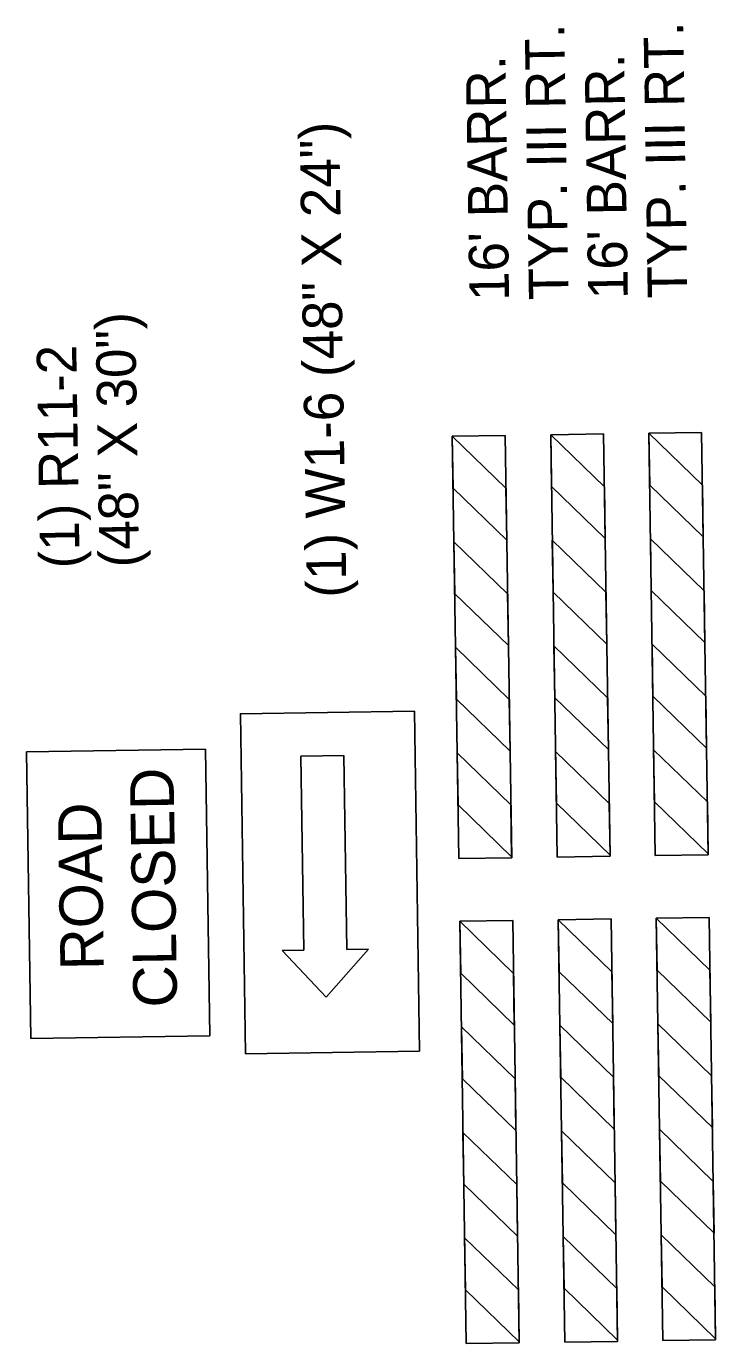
# Model space of a CAD drawing. Extents: x 1770018 to 1773492, y 718230 to 729141.
# Drawn here: x 1772247.2 to 1772351.6, y 718230.4 to 718430.1 of the extents above; entities that cross this region are included whole.
import ezdxf

# ---------------------------------------------------------------- set-up
doc = ezdxf.new("R2010")
doc.units = 0
doc.layers.add('R_MOT', color=7, linetype='Continuous')

msp = doc.modelspace()

# ---------------------------------------------------------------- linework, layer by layer
at = {"layer": 'R_MOT'}
for p, q in [((1772319.7, 718368.11), (1772311.67, 718367.99)), ((1772319.68, 718368.06), (1772319.63, 718368.11)), ((1772320.69, 718304.09), (1772319.7, 718368.11)), ((1772334.58, 718368.34), (1772326.57, 718368.22)), ((1772334.58, 718368.34), (1772326.57, 718368.22)), ((1772327.55, 718304.19), (1772326.57, 718368.22)), ((1772335.57, 718304.32), (1772334.58, 718368.34)), ((1772349.44, 718368.57), (1772341.42, 718368.45)), ((1772342.41, 718304.42), (1772341.42, 718368.45)), ((1772350.42, 718304.54), (1772349.44, 718368.57)), ((1772312.65, 718303.96), (1772311.67, 718367.99)), ((1772274.29, 718320.57), (1772247.15, 718320.15)), ((1772247.82, 718276.7), (1772247.15, 718320.15)), ((1772274.96, 718277.12), (1772274.29, 718320.57)), ((1772295.25, 718319.58), (1772288.71, 718319.48)), ((1772288.71, 718319.48), (1772289.16, 718290.1)), ((1772295.25, 718319.58), (1772295.71, 718290.2)), ((1772335.57, 718304.32), (1772327.55, 718304.19)), ((1772350.42, 718304.54), (1772342.41, 718304.42)), ((1772320.69, 718304.09), (1772312.65, 718303.96)), ((1772320.84, 718294.59), (1772312.8, 718294.47)), ((1772313.78, 718230.44), (1772312.8, 718294.47)), ((1772320.81, 718294.54), (1772320.77, 718294.59)), ((1772321.82, 718230.57), (1772320.84, 718294.59)), ((1772335.72, 718294.82), (1772327.7, 718294.7)), ((1772335.72, 718294.82), (1772327.7, 718294.7)), ((1772328.69, 718230.67), (1772327.7, 718294.7)), ((1772336.7, 718230.79), (1772335.72, 718294.82)), ((1772350.57, 718295.05), (1772342.55, 718294.92)), ((1772343.54, 718230.9), (1772342.55, 718294.92)), ((1772351.56, 718231.02), (1772350.57, 718295.05)), ((1772298.98, 718290.25), (1772292.55, 718282.97)), ((1772295.71, 718290.2), (1772298.98, 718290.25)), ((1772289.16, 718290.1), (1772285.89, 718290.05)), ((1772292.55, 718282.97), (1772285.89, 718290.05)), ((1772274.96, 718277.12), (1772247.82, 718276.7)), ((1772321.82, 718230.57), (1772313.78, 718230.44)), ((1772336.7, 718230.79), (1772328.69, 718230.67)), ((1772351.56, 718231.02), (1772343.54, 718230.9))]:
    msp.add_line(p, q, dxfattribs=at)
for points in [[(1772326.57, 718368.22), (1772326.71, 718360.35), (1772334.83, 718352.48), (1772334.71, 718360.33)], [(1772341.42, 718368.45), (1772341.57, 718360.58), (1772349.68, 718352.71), (1772349.56, 718360.55)], [(1772311.67, 718367.99), (1772311.81, 718360.12), (1772319.92, 718352.25), (1772319.8, 718360.1)], [(1772326.81, 718352.22), (1772326.96, 718344.35), (1772335.07, 718336.48), (1772334.95, 718344.33)], [(1772341.67, 718352.45), (1772341.81, 718344.58), (1772349.93, 718336.71), (1772349.81, 718344.56)], [(1772311.91, 718351.99), (1772312.06, 718344.12), (1772320.17, 718336.25), (1772320.05, 718344.1)], [(1772327.06, 718336.22), (1772327.21, 718328.35), (1772335.32, 718320.48), (1772335.2, 718328.33)], [(1772341.92, 718336.45), (1772342.06, 718328.58), (1772350.17, 718320.71), (1772350.05, 718328.56)], [(1772312.16, 718335.99), (1772312.3, 718328.12), (1772320.42, 718320.25), (1772320.3, 718328.1)], [(1772306.71, 718274.79), (1772305.92, 718326.32), (1772279.57, 718325.91), (1772280.36, 718274.39)], [(1772327.31, 718320.22), (1772327.45, 718312.35), (1772335.57, 718304.48), (1772335.45, 718312.33)], [(1772342.16, 718320.45), (1772342.31, 718312.58), (1772350.42, 718304.71), (1772350.3, 718312.56)], [(1772312.4, 718319.99), (1772312.55, 718312.12), (1772320.66, 718304.25), (1772320.54, 718312.1)], [(1772312.8, 718294.47), (1772312.94, 718286.6), (1772321.06, 718278.73), (1772320.94, 718286.57)], [(1772327.7, 718294.7), (1772327.85, 718286.82), (1772335.96, 718278.96), (1772335.84, 718286.8)], [(1772342.55, 718294.92), (1772342.7, 718287.05), (1772350.81, 718279.19), (1772350.69, 718287.03)], [(1772313.04, 718278.47), (1772313.19, 718270.6), (1772321.3, 718262.73), (1772321.18, 718270.58)], [(1772327.95, 718278.7), (1772328.09, 718270.83), (1772336.21, 718262.96), (1772336.09, 718270.81)], [(1772342.8, 718278.93), (1772342.95, 718271.06), (1772351.06, 718263.19), (1772350.94, 718271.03)], [(1772313.29, 718262.47), (1772313.44, 718254.6), (1772321.55, 718246.73), (1772321.43, 718254.58)], [(1772328.19, 718262.7), (1772328.34, 718254.83), (1772336.45, 718246.96), (1772336.33, 718254.81)], [(1772343.05, 718262.93), (1772343.19, 718255.06), (1772351.31, 718247.19), (1772351.19, 718255.04)], [(1772313.54, 718246.47), (1772313.68, 718238.6), (1772321.8, 718230.73), (1772321.68, 718238.58)], [(1772328.44, 718246.7), (1772328.59, 718238.83), (1772336.7, 718230.96), (1772336.58, 718238.81)], [(1772343.29, 718246.93), (1772343.44, 718239.06), (1772351.55, 718231.19), (1772351.43, 718239.04)]]:
    msp.add_lwpolyline(points, close=True, dxfattribs=at)

# ---------------------------------------------------------------- texts
for s, height, p in [('TYP. III RT.', 6, (1772347.27, 718388.95)), ('TYP. III RT.', 6, (1772329.28, 718388.67)), ("16' BARR.", 6, (1772320.28, 718388.53)), ("16' BARR.", 6, (1772338.27, 718388.81)), ('(1) W1-6 (48" X 24")', 6, (1772295.64, 718343.56)), ('(48" X 30")', 6, (1772264.23, 718348.14)), ('(1) R11-2', 6, (1772255.23, 718348)), ('CLOSED', 6.61, (1772270, 718281.44)), ('ROAD', 6.577, (1772258.89, 718287.1))]:
    msp.add_text(s, height=height, rotation=90.8827, dxfattribs=at).set_placement(p)

doc.saveas('drawing.dxf')
